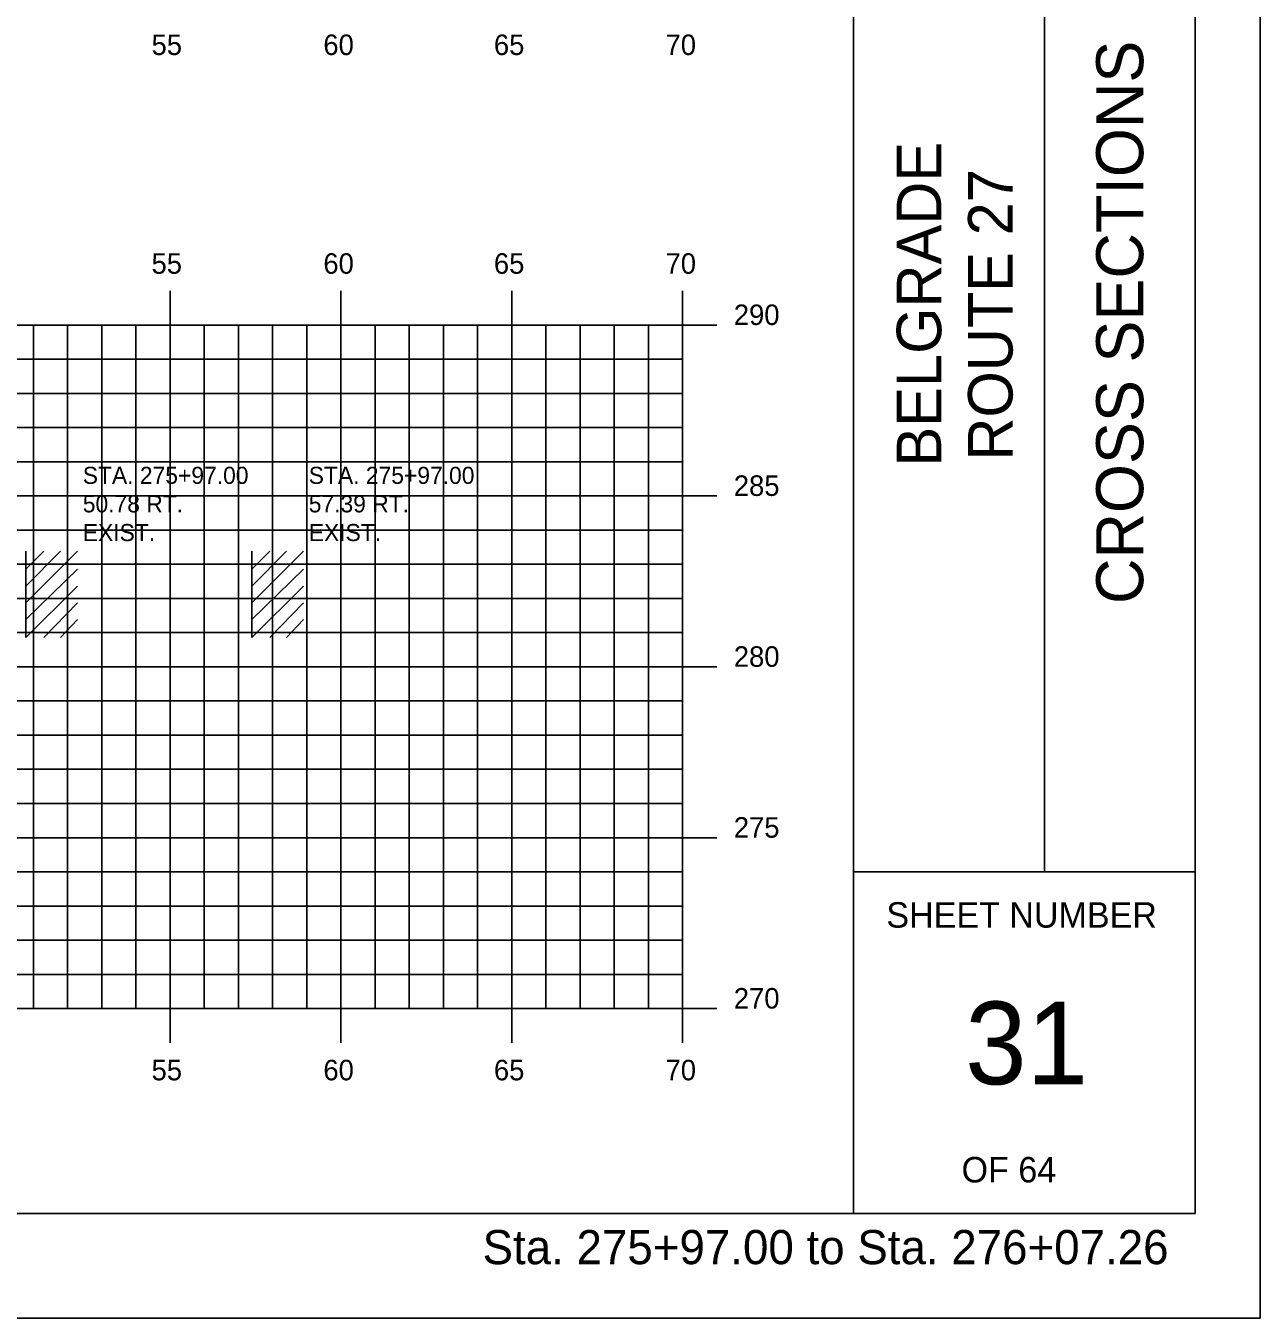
# Model space of a CAD drawing. Extents: x 853785 to 853955, y 366268 to 366378.
# Drawn here: x 853919.21 to 853955.34, y 366268.18 to 366305.99 of the extents above; entities that cross this region are included whole.
import ezdxf

# ---------------------------------------------------------------- set-up
doc = ezdxf.new("R2010")
doc.units = 0
for name, color, linetype in [('BORDER', 7, 'Continuous'), ('D_Text_Monospaced', 7, 'Continuous'), ('H_V ANNOTATION', 7, 'Continuous'), ('HIGHWAY_TITLE', 7, 'Continuous'), ('MAJOR', 7, 'Continuous'), ('MINOR', 7, 'Continuous'), ('PLOT BOUNDARY', 7, 'Continuous'), ('S_Buildings', 7, 'Continuous')]:
    doc.layers.add(name, color=color, linetype=linetype)

msp = doc.modelspace()

# ---------------------------------------------------------------- linework, layer by layer
at = {"layer": 'BORDER'}
for p, q in [((853943.435, 366271.236), (853943.435, 366376.239)), ((853953.435, 366271.236), (853953.435, 366376.236)), ((853949.027, 366281.239), (853949.027, 366316.239)), ((853943.435, 366281.239), (853953.435, 366281.239)), ((853793.435, 366271.236), (853953.435, 366271.236))]:
    msp.add_line(p, q, dxfattribs=at)
at = {"layer": 'MAJOR'}
for p, q in [((853923.435, 366298.238), (853923.435, 366297.236)), ((853928.435, 366298.238), (853928.435, 366297.236)), ((853933.435, 366298.238), (853933.435, 366297.236)), ((853938.435, 366298.238), (853938.435, 366297.236)), ((853798.435, 366297.236), (853938.435, 366297.236)), ((853798.435, 366297.236), (853938.435, 366297.236)), ((853923.435, 366277.236), (853923.435, 366297.236)), ((853928.435, 366277.236), (853928.435, 366297.236)), ((853933.435, 366277.236), (853933.435, 366297.236)), ((853939.437, 366297.236), (853937.433, 366297.236)), ((853938.435, 366277.236), (853938.435, 366297.236)), ((853938.435, 366277.236), (853938.435, 366297.236)), ((853798.435, 366292.236), (853938.435, 366292.236)), ((853939.437, 366292.236), (853937.433, 366292.236)), ((853798.435, 366287.236), (853938.435, 366287.236)), ((853939.437, 366287.236), (853937.433, 366287.236)), ((853798.435, 366282.236), (853938.435, 366282.236)), ((853939.437, 366282.236), (853937.433, 366282.236)), ((853798.435, 366277.236), (853938.435, 366277.236)), ((853798.435, 366277.236), (853938.435, 366277.236)), ((853923.435, 366276.234), (853923.435, 366277.236)), ((853928.435, 366276.234), (853928.435, 366277.236)), ((853933.435, 366276.234), (853933.435, 366277.236)), ((853939.437, 366277.236), (853937.433, 366277.236)), ((853938.435, 366276.234), (853938.435, 366277.236))]:
    msp.add_line(p, q, dxfattribs=at)
at = {"layer": 'MINOR'}
for p, q in [((853919.435, 366277.236), (853919.435, 366297.236)), ((853920.435, 366277.236), (853920.435, 366297.236)), ((853921.435, 366277.236), (853921.435, 366297.236)), ((853922.435, 366277.236), (853922.435, 366297.236)), ((853924.435, 366277.236), (853924.435, 366297.236)), ((853925.435, 366277.236), (853925.435, 366297.236)), ((853926.435, 366277.236), (853926.435, 366297.236)), ((853927.435, 366277.236), (853927.435, 366297.236)), ((853929.435, 366277.236), (853929.435, 366297.236)), ((853930.435, 366277.236), (853930.435, 366297.236)), ((853931.435, 366277.236), (853931.435, 366297.236)), ((853932.435, 366277.236), (853932.435, 366297.236)), ((853934.435, 366277.236), (853934.435, 366297.236)), ((853935.435, 366277.236), (853935.435, 366297.236)), ((853936.435, 366277.236), (853936.435, 366297.236)), ((853937.435, 366277.236), (853937.435, 366297.236)), ((853798.435, 366296.236), (853938.435, 366296.236)), ((853938.435, 366296.236), (853937.433, 366296.236)), ((853798.435, 366295.236), (853938.435, 366295.236)), ((853938.435, 366295.236), (853937.433, 366295.236)), ((853798.435, 366294.236), (853938.435, 366294.236)), ((853938.435, 366294.236), (853937.433, 366294.236)), ((853798.435, 366293.236), (853938.435, 366293.236)), ((853938.435, 366293.236), (853937.433, 366293.236)), ((853798.435, 366291.236), (853938.435, 366291.236)), ((853938.435, 366291.236), (853937.433, 366291.236)), ((853798.435, 366290.236), (853938.435, 366290.236)), ((853938.435, 366290.236), (853937.433, 366290.236)), ((853798.435, 366289.236), (853938.435, 366289.236)), ((853938.435, 366289.236), (853937.433, 366289.236)), ((853798.435, 366288.236), (853938.435, 366288.236)), ((853938.435, 366288.236), (853937.433, 366288.236)), ((853798.435, 366286.236), (853938.435, 366286.236)), ((853938.435, 366286.236), (853937.433, 366286.236)), ((853798.435, 366285.236), (853938.435, 366285.236)), ((853938.435, 366285.236), (853937.433, 366285.236)), ((853798.435, 366284.236), (853938.435, 366284.236)), ((853938.435, 366284.236), (853937.433, 366284.236)), ((853798.435, 366283.236), (853938.435, 366283.236)), ((853938.435, 366283.236), (853937.433, 366283.236)), ((853798.435, 366281.236), (853938.435, 366281.236)), ((853938.435, 366281.236), (853937.433, 366281.236)), ((853798.435, 366280.236), (853938.435, 366280.236)), ((853938.435, 366280.236), (853937.433, 366280.236)), ((853798.435, 366279.236), (853938.435, 366279.236)), ((853938.435, 366279.236), (853937.433, 366279.236)), ((853798.435, 366278.236), (853938.435, 366278.236)), ((853938.435, 366278.236), (853937.433, 366278.236))]:
    msp.add_line(p, q, dxfattribs=at)
at = {"layer": 'PLOT BOUNDARY'}
msp.add_lwpolyline([(853785.342, 366268.177), (853955.342, 366268.177), (853955.342, 366378.177), (853785.342, 366378.177)], close=True, dxfattribs=at)
at = {"layer": 'S_Buildings'}
for p, q in [((853919.212, 366288.09), (853919.212, 366290.616)), ((853919.212, 366289.107), (853920.721, 366290.616)), ((853919.212, 366289.599), (853920.229, 366290.616)), ((853919.212, 366290.091), (853919.737, 366290.616)), ((853925.827, 366288.09), (853925.827, 366290.616)), ((853925.827, 366289.107), (853927.336, 366290.616)), ((853925.827, 366289.599), (853926.844, 366290.616)), ((853925.827, 366290.091), (853926.352, 366290.616)), ((853919.212, 366288.615), (853920.721, 366290.091)), ((853925.827, 366288.615), (853927.336, 366290.091)), ((853919.212, 366288.09), (853920.721, 366289.599)), ((853925.827, 366288.09), (853927.336, 366289.599)), ((853919.737, 366288.09), (853920.721, 366289.107)), ((853926.352, 366288.09), (853927.336, 366289.107)), ((853920.229, 366288.09), (853920.721, 366288.615)), ((853926.844, 366288.09), (853927.336, 366288.615))]:
    msp.add_line(p, q, dxfattribs=at)

# ---------------------------------------------------------------- texts
at = {"layer": 'BORDER'}
for s, height, rotation, p in [('CROSS SECTIONS', 1.37787, 90, (853951.92, 366289.073)), ('SHEET NUMBER', 0.74527, 360, (853944.401, 366279.603)), ('31', 2.4194, 360, (853946.707, 366275.019)), ('OF 64', 0.7453, 360, (853946.602, 366272.149))]:
    msp.add_text(s, height=height, rotation=rotation, dxfattribs=at).set_placement(p)
at = {"layer": 'D_Text_Monospaced'}
for s, height, p in [('STA. 275+97.00', 0.49998, (853920.879, 366292.588)), ('STA. 275+97.00', 0.49998, (853927.493, 366292.588)), ('50.78 RT.', 0.5, (853920.879, 366291.754)), ('57.39 RT.', 0.5, (853927.493, 366291.754)), ('EXIST. ', 0.5, (853920.879, 366290.914)), ('EXIST. ', 0.5, (853927.493, 366290.914))]:
    msp.add_text(s, height=height, dxfattribs=at).set_placement(p)
at = {"layer": 'H_V ANNOTATION'}
for s, height, p in [('55', 0.6, (853922.892, 366305.136)), ('60', 0.6, (853927.921, 366305.136)), ('65', 0.6, (853932.913, 366305.136)), ('70', 0.6, (853937.937, 366305.136)), ('55', 0.6, (853922.892, 366298.736)), ('60', 0.6, (853927.921, 366298.736)), ('65', 0.6, (853932.913, 366298.736)), ('70', 0.6, (853937.937, 366298.736)), ('290', 0.6, (853939.935, 366297.236)), ('285', 0.6, (853939.935, 366292.236)), ('280', 0.6, (853939.935, 366287.236)), ('275', 0.6, (853939.935, 366282.236)), ('270', 0.6, (853939.935, 366277.236)), ('55', 0.6, (853922.892, 366275.136)), ('60', 0.6, (853927.921, 366275.136)), ('65', 0.6, (853932.913, 366275.136)), ('70', 0.6, (853937.937, 366275.136)), ('Sta. 275+97.00 to Sta. 276+07.26', 1.0002, (853932.581, 366269.756))]:
    msp.add_text(s, height=height, dxfattribs=at).set_placement(p)
at = {"layer": 'HIGHWAY_TITLE'}
for s, p in [('BELGRADE', (853946.008, 366293.095)), ('ROUTE 27', (853948.095, 366293.269))]:
    msp.add_text(s, height=1.3043, rotation=90, dxfattribs=at).set_placement(p)

doc.saveas('drawing.dxf')
